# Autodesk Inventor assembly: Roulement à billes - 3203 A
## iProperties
Shininess: 64.0
Length Units: 11269
Angle Units: 11279
Time Units: 11290
Mass Units: 11283
Length Display Precision: 3
Angle Display Precision: 2
Compacted: True
Created: 2005-02
Part Number: Roulement à billes - 3203 A
Document SubType Name: Assembly
Designer: LEGERET Philippe
Catalog Web Link: www.traceparts.com
Description: Roulement à billes à contact oblique à deux rangées - pour arbre Ø17
Vendor: SKF
Density: 0.0
Volumn: 0.0
Area: 0.0
PropertySet Name: Model Information
Control State: 0
Master: False
Checked Out: False
REFERENCE: 3203 A
Author: Trace Parts S.A.
